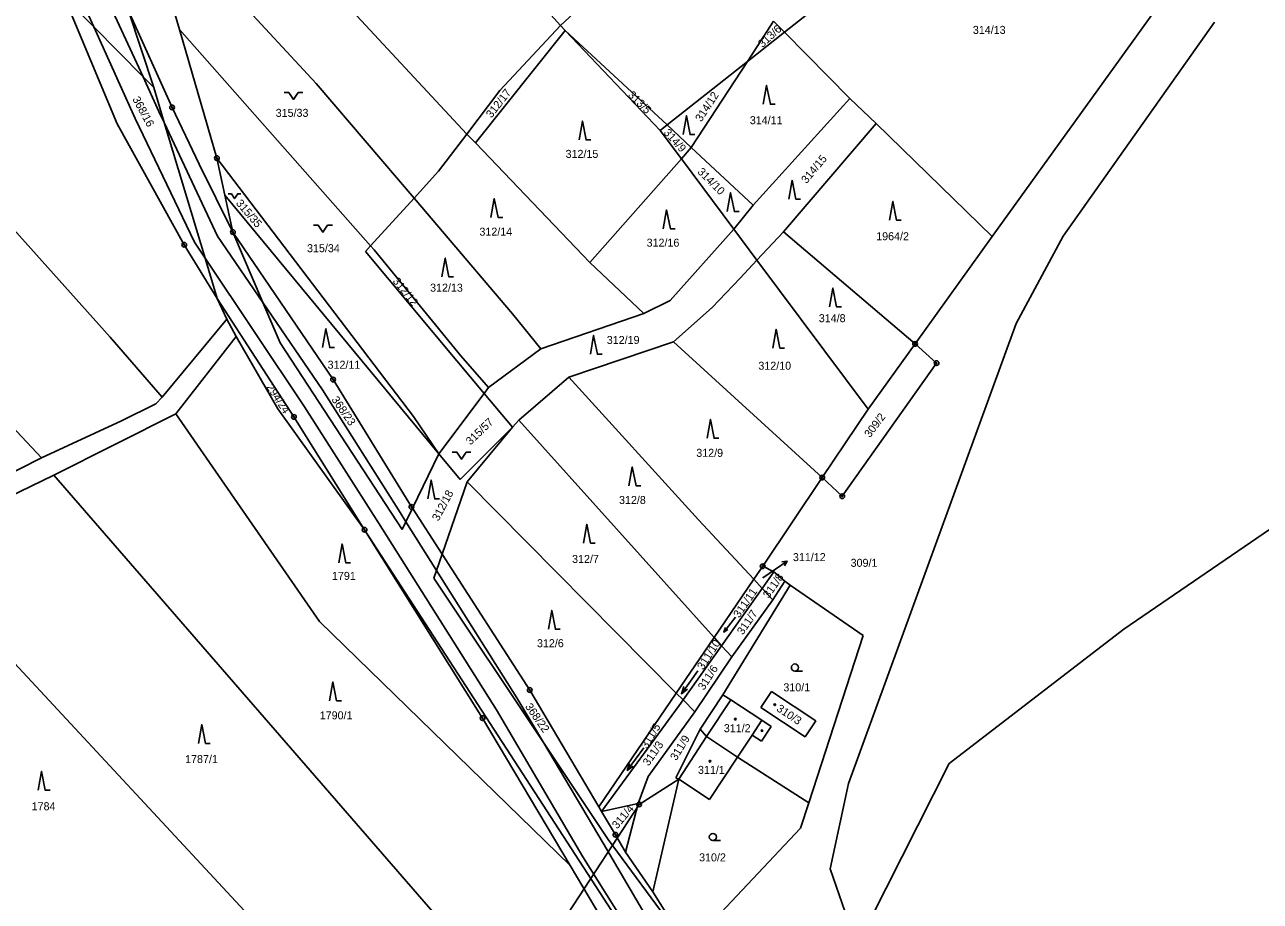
# Model space of a CAD drawing. Extents: x -762263 to -760336, y -1154405 to -1152076.
# Drawn here: x -761124.8 to -760862.4, y -1153687.5 to -1153501.2 of the extents above; entities that cross this region are included whole.
import ezdxf

# ---------------------------------------------------------------- set-up
doc = ezdxf.new("R2010")
doc.units = 0
for name, color, linetype in [('Vrstva 1', 7, 'Continuous'), ('Vrstva 12', 7, 'Continuous'), ('Vrstva 16', 7, 'Continuous'), ('Vrstva 18', 7, 'Continuous'), ('Vrstva 19', 7, 'Continuous'), ('Vrstva 24', 7, 'Continuous'), ('Vrstva 25', 7, 'Continuous'), ('Vrstva 26', 7, 'Continuous'), ('Vrstva 4', 7, 'Continuous'), ('Vrstva 6', 7, 'Continuous')]:
    doc.layers.add(name, color=color, linetype=linetype)

msp = doc.modelspace()

# ---------------------------------------------------------------- linework, layer by layer
at = {"layer": 'Vrstva 1'}
for p, q in [((-761091.93, -1153502.27), (-761100.45, -1153473.04)), ((-760987.13, -1153479.09), (-761010.99, -1153501.39)), ((-760963.41, -1153502.81), (-760952.38, -1153494.09)), ((-760882.41, -1153494.9), (-760919.31, -1153546.23)), ((-761105.15, -1153522.27), (-761116.32, -1153495.42)), ((-761116.32, -1153495.42), (-761110.14, -1153501.67)), ((-761102.76, -1153498.28), (-761097.38, -1153514.59)), ((-761102.76, -1153498.28), (-761093.48, -1153518.8)), ((-761110.14, -1153501.67), (-761099.65, -1153512.3)), ((-761083.97, -1153529.55), (-761091.93, -1153502.27)), ((-761023.87, -1153515.18), (-761010.99, -1153501.39)), ((-761010.99, -1153501.39), (-761009.97, -1153502.47)), ((-761009.97, -1153502.47), (-760989.84, -1153523.7)), ((-760971.3, -1153509.04), (-760963.41, -1153502.81)), ((-760904.22, -1153546.18), (-760872.1, -1153500.69)), ((-760988.36, -1153522.53), (-760971.3, -1153509.04)), ((-761099.65, -1153512.3), (-761097.38, -1153514.59)), ((-761097.38, -1153514.59), (-761095.14, -1153522.03)), ((-761030.9, -1153524.45), (-761023.87, -1153515.18)), ((-761093.48, -1153518.8), (-761087.72, -1153530.82)), ((-761090.9, -1153547.97), (-761105.15, -1153522.27)), ((-761095.14, -1153522.03), (-761086.48, -1153550.81)), ((-760989.84, -1153523.7), (-760988.36, -1153522.53)), ((-760989.84, -1153523.7), (-760985.32, -1153529.75)), ((-761036.88, -1153532.35), (-761030.9, -1153524.45)), ((-761080.57, -1153545.28), (-761087.72, -1153530.82)), ((-761082.27, -1153537.41), (-761083.97, -1153529.55)), ((-760985.32, -1153529.75), (-760974.21, -1153544.64)), ((-761036.88, -1153532.35), (-761042.1, -1153538.08)), ((-761080.57, -1153545.28), (-761082.27, -1153537.41)), ((-761036.81, -1153592.37), (-761082.27, -1153537.41)), ((-761042.1, -1153538.08), (-761051.32, -1153548.2)), ((-760974.21, -1153544.64), (-760969.27, -1153551.26)), ((-761059.28, -1153576.62), (-761080.57, -1153545.28)), ((-761074.19, -1153560.24), (-761080.57, -1153545.28)), ((-760919.31, -1153546.23), (-760935.7, -1153569.04)), ((-760914.21, -1153564.73), (-760904.22, -1153546.18)), ((-761083.9, -1153559.37), (-761090.9, -1153547.97)), ((-761051.32, -1153548.2), (-761052.43, -1153549.41)), ((-761052.43, -1153549.41), (-761032.98, -1153572.64)), ((-761086.48, -1153550.81), (-761083.9, -1153559.37)), ((-760969.27, -1153551.26), (-760945.65, -1153582.89)), ((-761083.9, -1153559.37), (-761067.6, -1153584.56)), ((-761070.53, -1153568.81), (-761074.19, -1153560.24)), ((-760949.86, -1153662.45), (-760914.21, -1153564.73)), ((-761070.53, -1153568.81), (-761044.6, -1153608.48)), ((-760935.7, -1153569.04), (-760945.65, -1153582.89)), ((-760931.12, -1153573.12), (-760935.7, -1153569.04)), ((-761032.98, -1153572.64), (-761027.19, -1153579.55)), ((-760951.17, -1153601.41), (-760931.12, -1153573.12)), ((-761042.66, -1153603.67), (-761059.28, -1153576.62)), ((-761027.19, -1153579.55), (-761021.16, -1153586.76)), ((-760945.65, -1153582.89), (-760955.42, -1153597.46)), ((-760824.24, -1153583.74), (-760891.34, -1153629.63)), ((-761052.6, -1153608.54), (-761067.6, -1153584.56)), ((-761032.28, -1153597.85), (-761021.16, -1153586.76)), ((-761032.28, -1153597.85), (-761036.81, -1153592.37)), ((-760955.42, -1153597.46), (-760968.06, -1153616.3)), ((-760955.42, -1153597.46), (-760951.17, -1153601.41)), ((-761042.46, -1153603.97), (-761043.82, -1153606.84)), ((-761042.46, -1153603.97), (-761042.66, -1153603.67)), ((-761036.15, -1153613.74), (-761042.46, -1153603.97)), ((-761043.82, -1153606.84), (-761044.6, -1153608.48)), ((-760991.27, -1153703.15), (-761052.6, -1153608.54)), ((-761027.56, -1153648.57), (-761052.6, -1153608.54)), ((-761036.15, -1153613.74), (-761037.31, -1153617.17)), ((-761017.51, -1153642.59), (-761036.15, -1153613.74)), ((-761037.31, -1153617.17), (-761037.88, -1153618.84)), ((-760969.94, -1153619.06), (-760968.06, -1153616.3)), ((-760968.14, -1153621), (-760965.66, -1153617.51)), ((-760965.66, -1153617.51), (-760968.06, -1153616.3)), ((-760965.66, -1153617.51), (-760963.32, -1153619.43)), ((-761037.88, -1153618.84), (-761014.63, -1153653.72)), ((-760978.35, -1153631.41), (-760969.94, -1153619.06)), ((-760976.78, -1153633.18), (-760968.14, -1153621)), ((-760962.22, -1153620.34), (-760976.49, -1153643.6)), ((-760963.32, -1153619.43), (-760962.22, -1153620.34)), ((-760962.22, -1153620.34), (-760946.74, -1153631.04)), ((-760978.35, -1153631.41), (-760986.41, -1153643.24)), ((-760958.24, -1153666.57), (-760946.74, -1153631.04)), ((-760891.34, -1153629.63), (-760928.42, -1153658.17)), ((-760976.78, -1153633.18), (-760984.96, -1153644.7)), ((-761002.85, -1153667.38), (-761017.51, -1153642.59)), ((-760986.41, -1153643.24), (-761002.85, -1153667.38)), ((-760976.49, -1153643.6), (-760981.33, -1153650.92)), ((-760976.49, -1153643.6), (-760974.81, -1153644.7)), ((-760968.44, -1153646.31), (-760966.21, -1153642.88)), ((-760966.21, -1153642.88), (-760956.77, -1153649.11)), ((-760985.78, -1153645.85), (-761002.26, -1153668.4)), ((-760984.96, -1153644.7), (-760985.78, -1153645.85)), ((-760968.24, -1153649.01), (-760974.81, -1153644.7)), ((-760959.01, -1153652.51), (-760968.44, -1153646.31)), ((-761027.56, -1153648.57), (-761008.97, -1153679.88)), ((-760966.25, -1153650.31), (-760968.24, -1153649.01)), ((-760956.77, -1153649.11), (-760959.01, -1153652.51)), ((-760981.33, -1153650.92), (-760986.48, -1153661.25)), ((-760981.33, -1153650.92), (-760979.98, -1153652.45)), ((-760979.98, -1153652.45), (-760973.42, -1153656.89)), ((-760973.42, -1153656.89), (-760970.32, -1153652.18)), ((-760970.32, -1153652.18), (-760968.33, -1153653.49)), ((-760968.33, -1153653.49), (-760966.25, -1153650.31)), ((-761014.63, -1153653.72), (-761000.86, -1153674.38)), ((-760973.42, -1153656.89), (-760979.33, -1153665.86)), ((-760958.24, -1153666.57), (-760973.42, -1153656.89)), ((-760928.42, -1153658.17), (-760945.15, -1153691.28)), ((-760985.85, -1153661.54), (-760991.4, -1153685.47)), ((-760986.48, -1153661.25), (-760985.85, -1153661.54)), ((-760979.33, -1153665.86), (-760985.85, -1153661.54)), ((-760953.71, -1153680.58), (-760949.86, -1153662.45)), ((-761002.26, -1153668.4), (-761002.85, -1153667.38)), ((-761002.26, -1153668.4), (-760994.47, -1153666.7)), ((-760997.21, -1153677.06), (-760994.47, -1153666.7)), ((-760959.99, -1153671.97), (-760958.24, -1153666.57)), ((-760999.33, -1153673.35), (-761002.26, -1153668.4)), ((-760999.33, -1153673.35), (-760997.21, -1153677.06)), ((-760983.9, -1153697.32), (-760959.99, -1153671.97)), ((-760983.9, -1153697.32), (-761000.86, -1153674.38)), ((-760997.21, -1153677.06), (-760991.4, -1153685.47)), ((-761008.97, -1153679.88), (-760995.71, -1153702.01)), ((-760945.38, -1153704.81), (-760953.71, -1153680.58)), ((-760991.4, -1153685.47), (-760983.9, -1153697.32))]:
    msp.add_line(p, q, dxfattribs=at)
at = {"layer": 'Vrstva 12'}
for p in [(-760985.85, -1153661.54), (-761009.38, -1153690)]:
    msp.add_line(p, (-760994.3, -1153666.9), dxfattribs=at)
at = {"layer": 'Vrstva 16'}
for p in [(-760962.875, -1153615.2), (-760968.02, -1153618.77)]:
    msp.add_line(p, (-760965.34, -1153616.91), dxfattribs=at)
msp.add_lwpolyline([(-760963.982, -1153615.359), (-760962.875, -1153615.2), (-760963.412, -1153616.181)], dxfattribs=at)
at = {"layer": 'Vrstva 24'}
for centre, radius in [((-761093.48, -1153518.8), 0.5), ((-761093.48, -1153518.8), 0.1), ((-761083.97, -1153529.55), 0.5), ((-761083.97, -1153529.55), 0.1), ((-761080.57, -1153545.28), 0.5), ((-761090.9, -1153547.97), 0.5), ((-761080.57, -1153545.28), 0.1), ((-761090.9, -1153547.97), 0.1), ((-760935.7, -1153569.04), 0.5), ((-760935.7, -1153569.04), 0.1), ((-760931.12, -1153573.12), 0.5), ((-760931.12, -1153573.12), 0.1), ((-761059.28, -1153576.62), 0.5), ((-761059.28, -1153576.62), 0.1), ((-761067.6, -1153584.56), 0.5), ((-761067.6, -1153584.56), 0.1), ((-760955.42, -1153597.46), 0.5), ((-760955.42, -1153597.46), 0.1), ((-760951.17, -1153601.41), 0.5), ((-760951.17, -1153601.41), 0.1), ((-761042.66, -1153603.67), 0.5), ((-761042.66, -1153603.67), 0.1), ((-761052.6, -1153608.54), 0.5), ((-761052.6, -1153608.54), 0.1), ((-760968.06, -1153616.3), 0.5), ((-760968.06, -1153616.3), 0.1), ((-761017.51, -1153642.59), 0.5), ((-761017.51, -1153642.59), 0.1), ((-761027.56, -1153648.57), 0.5), ((-761027.56, -1153648.57), 0.1), ((-760999.33, -1153673.35), 0.5), ((-760999.33, -1153673.35), 0.1)]:
    msp.add_circle(centre, radius, dxfattribs=at)
at = {"layer": 'Vrstva 25'}
for p, q in [((-760961.22, -1153638.56), (-760959.62, -1153638.56)), ((-760978.64, -1153674.57), (-760977.04, -1153674.57))]:
    msp.add_line(p, q, dxfattribs=at)
for points in [[(-761069.71, -1153515.6), (-761068.71, -1153515.6), (-761067.71, -1153517.1), (-761066.71, -1153515.6), (-761065.71, -1153515.6)], [(-760967.93, -1153518.11), (-760967.23, -1153514.11), (-760966.43, -1153518.11), (-760965.43, -1153518.11)], [(-760984.97, -1153524.56), (-760984.27, -1153520.56), (-760983.47, -1153524.56), (-760982.47, -1153524.56)], [(-761007.05, -1153525.7), (-761006.35, -1153521.7), (-761005.55, -1153525.7), (-761004.55, -1153525.7)], [(-760962.52, -1153538.28), (-760961.82, -1153534.28), (-760961.02, -1153538.28), (-760960.02, -1153538.28)], [(-760975.57, -1153540.93), (-760974.87, -1153536.93), (-760974.07, -1153540.93), (-760973.07, -1153540.93)], [(-761081.56, -1153537.145), (-761080.89, -1153537.145), (-761080.22, -1153538.15), (-761079.55, -1153537.145), (-761078.88, -1153537.145)], [(-761025.76, -1153542.18), (-761025.06, -1153538.18), (-761024.26, -1153542.18), (-761023.26, -1153542.18)], [(-760941.11, -1153542.77), (-760940.41, -1153538.77), (-760939.61, -1153542.77), (-760938.61, -1153542.77)], [(-760989.16, -1153544.57), (-760988.46, -1153540.57), (-760987.66, -1153544.57), (-760986.66, -1153544.57)], [(-761063.45, -1153543.83), (-761062.45, -1153543.83), (-761061.45, -1153545.33), (-761060.45, -1153543.83), (-761059.45, -1153543.83)], [(-761036.19, -1153554.8), (-761035.49, -1153550.8), (-761034.69, -1153554.8), (-761033.69, -1153554.8)], [(-760953.85, -1153561.17), (-760953.15, -1153557.17), (-760952.35, -1153561.17), (-760951.35, -1153561.17)], [(-761061.51, -1153569.83), (-761060.81, -1153565.83), (-761060.01, -1153569.83), (-761059.01, -1153569.83)], [(-760965.91, -1153569.92), (-760965.21, -1153565.92), (-760964.41, -1153569.92), (-760963.41, -1153569.92)], [(-761004.66, -1153571.24), (-761003.96, -1153567.24), (-761003.16, -1153571.24), (-761002.16, -1153571.24)], [(-760979.87, -1153589.1), (-760979.17, -1153585.1), (-760978.37, -1153589.1), (-760977.37, -1153589.1)], [(-761034.01, -1153592.06), (-761033.01, -1153592.06), (-761032.01, -1153593.56), (-761031.01, -1153592.06), (-761030.01, -1153592.06)], [(-760996.46, -1153599.18), (-760995.76, -1153595.18), (-760994.96, -1153599.18), (-760993.96, -1153599.18)], [(-761039.19, -1153601.97), (-761038.49, -1153597.97), (-761037.69, -1153601.97), (-761036.69, -1153601.97)], [(-761006.11, -1153611.38), (-761005.41, -1153607.38), (-761004.61, -1153611.38), (-761003.61, -1153611.38)], [(-761058.09, -1153615.54), (-761057.39, -1153611.54), (-761056.59, -1153615.54), (-761055.59, -1153615.54)], [(-761013.57, -1153629.67), (-761012.87, -1153625.67), (-761012.07, -1153629.67), (-761011.07, -1153629.67)], [(-760973.831, -1153627.125), (-760976.329, -1153630.275), (-760975.442, -1153629.696)], [(-760976.329, -1153630.275), (-760975.967, -1153629.279)], [(-760981.818, -1153638.487), (-760985.302, -1153643.373), (-760984.024, -1153642.442)], [(-761060.04, -1153644.88), (-761059.34, -1153640.88), (-761058.54, -1153644.88), (-761057.54, -1153644.88)], [(-760985.302, -1153643.373), (-760984.838, -1153641.861)], [(-761087.88, -1153653.92), (-761087.18, -1153649.92), (-761086.38, -1153653.92), (-761085.38, -1153653.92)], [(-760993.265, -1153654.859), (-760996.835, -1153659.681), (-760995.541, -1153658.773)], [(-761121.91, -1153663.89), (-761121.21, -1153659.89), (-761120.41, -1153663.89), (-761119.41, -1153663.89)], [(-760996.835, -1153659.681), (-760996.344, -1153658.178)]]:
    msp.add_lwpolyline(points, dxfattribs=at)
for centre, radius in [((-760961.22, -1153637.81), 0.75), ((-760965.49, -1153645.71), 0.175), ((-760973.88, -1153648.78), 0.175), ((-760968.19, -1153651.22), 0.175), ((-760979.24, -1153657.72), 0.175), ((-760978.64, -1153673.82), 0.75)]:
    msp.add_circle(centre, radius, dxfattribs=at)
at = {"layer": 'Vrstva 26'}
msp.add_circle((-760994.3, -1153666.9), 0.5, dxfattribs=at)
at = {"layer": 'Vrstva 4'}
for p, q in [((-761110.14, -1153501.67), (-761117.86, -1153484.57)), ((-761099.65, -1153512.3), (-761113.39, -1153482.44)), ((-761101.36, -1153521.14), (-761110.14, -1153501.67)), ((-761096.27, -1153519.63), (-761099.65, -1153512.3)), ((-761101.36, -1153521.14), (-761088.75, -1153547.41)), ((-761095.14, -1153522.03), (-761096.27, -1153519.63)), ((-761083.81, -1153546.12), (-761095.14, -1153522.03)), ((-761088.75, -1153547.41), (-761086.48, -1153550.81)), ((-761074.19, -1153560.24), (-761083.81, -1153546.12)), ((-761086.48, -1153550.81), (-761065.36, -1153582.42)), ((-761061.55, -1153578.78), (-761074.19, -1153560.24)), ((-761061.55, -1153578.78), (-761045.07, -1153604.85)), ((-761049.66, -1153607.1), (-761065.36, -1153582.42)), ((-761045.07, -1153604.85), (-761043.82, -1153606.84)), ((-761024.58, -1153646.8), (-761049.66, -1153607.1)), ((-761043.82, -1153606.84), (-761037.31, -1153617.17)), ((-761020.27, -1153644.23), (-761037.31, -1153617.17)), ((-761014.63, -1153653.72), (-761020.27, -1153644.23)), ((-761024.58, -1153646.8), (-761006.25, -1153678.03)), ((-760979.98, -1153652.45), (-760974.81, -1153644.7)), ((-760970.32, -1153652.18), (-760968.24, -1153649.01)), ((-760985.85, -1153661.54), (-760979.98, -1153652.45)), ((-761001.92, -1153675.11), (-761014.63, -1153653.72)), ((-760987.93, -1153698.92), (-761001.92, -1153675.11)), ((-761006.25, -1153678.03), (-760992.1, -1153700.58))]:
    msp.add_line(p, q, dxfattribs=at)
at = {"layer": 'Vrstva 6'}
for p, q in [((-761100.45, -1153473.04), (-761062.86, -1153513.72)), ((-761031.98, -1153477.92), (-761010.99, -1153501.39)), ((-761183.36, -1153481.98), (-761106.64, -1153567.61)), ((-761058.49, -1153494.72), (-761030.9, -1153524.45)), ((-761051.32, -1153548.2), (-761091.93, -1153502.27)), ((-761029.04, -1153526.34), (-761009.97, -1153502.47)), ((-760988.36, -1153522.53), (-761009.97, -1153502.47)), ((-760965.76, -1153500.49), (-760971.3, -1153509.04)), ((-760965.76, -1153500.49), (-760963.41, -1153502.81)), ((-760963.41, -1153502.81), (-760949.55, -1153516.89)), ((-760971.3, -1153509.04), (-760983.23, -1153527.3)), ((-761062.86, -1153513.72), (-761042.1, -1153538.08)), ((-760970.05, -1153539.54), (-760949.55, -1153516.89)), ((-760943.93, -1153522.21), (-760949.55, -1153516.89)), ((-760983.23, -1153527.3), (-760988.36, -1153522.53)), ((-760963.63, -1153545.2), (-760943.93, -1153522.21)), ((-760943.93, -1153522.21), (-760919.31, -1153546.23)), ((-761030.9, -1153524.45), (-761029.04, -1153526.34)), ((-761004.79, -1153551.76), (-761029.04, -1153526.34)), ((-760983.23, -1153527.3), (-760985.32, -1153529.75)), ((-760983.23, -1153527.3), (-760970.05, -1153539.54)), ((-761083.97, -1153529.55), (-761042.21, -1153584.5)), ((-760985.32, -1153529.75), (-761004.79, -1153551.76)), ((-761171.68, -1153539.67), (-761121.21, -1153593.28)), ((-761042.1, -1153538.08), (-761021.17, -1153562.63)), ((-760974.21, -1153544.64), (-760970.05, -1153539.54)), ((-760987.68, -1153559.81), (-760974.21, -1153544.64)), ((-760963.63, -1153545.2), (-760969.27, -1153551.26)), ((-760963.63, -1153545.2), (-760935.7, -1153569.04)), ((-761050.58, -1153549.04), (-761051.32, -1153548.2)), ((-761032.16, -1153571.59), (-761050.58, -1153549.04)), ((-760993.32, -1153562.55), (-761004.79, -1153551.76)), ((-760969.27, -1153551.26), (-760972.84, -1153555.1)), ((-760972.84, -1153555.1), (-760978.81, -1153561.3)), ((-761083.9, -1153559.37), (-761081.89, -1153563.82)), ((-760993.32, -1153562.55), (-760987.68, -1153559.81)), ((-761021.17, -1153562.63), (-761015.16, -1153570.12)), ((-761015.16, -1153570.12), (-760993.32, -1153562.55)), ((-760978.81, -1153561.3), (-760986.97, -1153568.59)), ((-761095.56, -1153580.38), (-761081.89, -1153563.82)), ((-761081.89, -1153563.82), (-761079.85, -1153567.48)), ((-761095.56, -1153580.38), (-761106.64, -1153567.61)), ((-761092.7, -1153583.88), (-761079.85, -1153567.48)), ((-761079.85, -1153567.48), (-761071.01, -1153582.83)), ((-761026.32, -1153578.32), (-761015.16, -1153570.12)), ((-761009.22, -1153576.14), (-760986.97, -1153568.59)), ((-760986.97, -1153568.59), (-760955.42, -1153597.46)), ((-761026.32, -1153578.32), (-761032.16, -1153571.59)), ((-761019.83, -1153585.25), (-761009.22, -1153576.14)), ((-761009.22, -1153576.14), (-760981.67, -1153606.44)), ((-761026.32, -1153578.32), (-761027.19, -1153579.55)), ((-761096.97, -1153581.79), (-761095.56, -1153580.38)), ((-761027.19, -1153579.55), (-761036.81, -1153592.37)), ((-761118.57, -1153596.92), (-761092.7, -1153583.88)), ((-761104.21, -1153585.38), (-761096.97, -1153581.79)), ((-761062.18, -1153628.04), (-761092.7, -1153583.88)), ((-761071.01, -1153582.83), (-761052.6, -1153608.54)), ((-761121.21, -1153593.28), (-761104.21, -1153585.38)), ((-761042.21, -1153584.5), (-761036.81, -1153592.37)), ((-761030.79, -1153598.33), (-761021.16, -1153586.76)), ((-761021.16, -1153586.76), (-761019.83, -1153585.25)), ((-761019.83, -1153585.25), (-760978.35, -1153631.41)), ((-761152.76, -1153609.11), (-761121.21, -1153593.28)), ((-761036.81, -1153592.37), (-761042.46, -1153603.97)), ((-761150.08, -1153612.09), (-761118.57, -1153596.92)), ((-761118.57, -1153596.92), (-761028.35, -1153700.96)), ((-761036.15, -1153613.74), (-761030.79, -1153598.33)), ((-760986.41, -1153643.24), (-761030.79, -1153598.33)), ((-760981.67, -1153606.44), (-760969.94, -1153619.06)), ((-761150.08, -1153612.09), (-761049.56, -1153720.16)), ((-760969.94, -1153619.06), (-760968.14, -1153621)), ((-760968.14, -1153621), (-760965.91, -1153623.4)), ((-760965.91, -1153623.4), (-760963.32, -1153619.43)), ((-760974.59, -1153635.53), (-760965.91, -1153623.4)), ((-761008.97, -1153679.88), (-761062.18, -1153628.04)), ((-760978.35, -1153631.41), (-760976.78, -1153633.18)), ((-760976.78, -1153633.18), (-760974.59, -1153635.53)), ((-760982.49, -1153647.2), (-760974.59, -1153635.53)), ((-760984.96, -1153644.7), (-760986.41, -1153643.24)), ((-760992.41, -1153660.98), (-760982.49, -1153647.2)), ((-760982.49, -1153647.2), (-760984.96, -1153644.7)), ((-760994.47, -1153666.7), (-760992.41, -1153660.98))]:
    msp.add_line(p, q, dxfattribs=at)

# ---------------------------------------------------------------- texts
at = {"layer": 'Vrstva 16'}
msp.add_text('311/12', height=1.7, dxfattribs=at).set_placement((-760961.633, -1153615.2))
at = {"layer": 'Vrstva 18'}
for s, rotation, p in [('313/6', 42.39888, (-760968.087, -1153506.198)), ('312/17', 51.90998, (-761025.658, -1153521.172)), ('313/5', 315.47056, (-760996.797, -1153516.322)), ('314/12', 56.72282, (-760981.108, -1153521.989)), ('368/16', 298.33913, (-761101.977, -1153517.009)), ('314/9', 311.97552, (-760989.212, -1153524.252)), ('314/15', 50.1911, (-760958.739, -1153535.095)), ('314/10', 315.01219, (-760982.024, -1153532.627)), ('315/35', 310.54313, (-761080.038, -1153539.228)), ('312/12', 308.65236, (-761046.746, -1153555.761)), ('294/24', 303.09467, (-761073.551, -1153578.223)), ('368/23', 304.69896, (-761059.715, -1153580.895)), ('309/2', 52.9413, (-760945.282, -1153589.109)), ('315/57', 43.71668, (-761030.12, -1153590.656)), ('312/18', 62.22322, (-761036.901, -1153606.822)), ('311/8', 54.88936, (-760966.766, -1153623.237)), ('311/11', 55.51961, (-760973.045, -1153627.402)), ('311/7', 55.51961, (-760972.266, -1153631.015)), ('311/10', 57.18119, (-760980.7, -1153638.443)), ('311/6', 57.18119, (-760980.531, -1153642.773)), ('368/22', 304.92814, (-761018.594, -1153646.115)), ('311/5', 58.3844, (-760992.635, -1153655.215)), ('311/9', 58.55629, (-760986.403, -1153657.719)), ('311/3', 55.23313, (-760992.28, -1153658.861)), ('311/4', 49.84733, (-760998.947, -1153672.219))]:
    msp.add_text(s, height=1.7, rotation=rotation, dxfattribs=at).set_placement(p)
for s, height, p in [('314/13', 1.7, (-760923.42, -1153503.17)), ('315/33', 1.7, (-761071.482, -1153520.8)), ('314/11', 1.7, (-760970.785, -1153522.36)), ('312/15', 1.7, (-761009.914, -1153529.52)), ('312/14', 1.7, (-761028.217, -1153546.05)), ('312/16', 1.7, (-760992.707, -1153548.39)), ('1964/2', 1.7, (-760943.948, -1153547.02)), ('315/34', 1.7, (-761064.825, -1153549.56)), ('312/13', 1.7, (-761038.694, -1153557.95)), ('314/8', 1.7, (-760956.142, -1153564.43)), ('312/19', 1.7, (-761001.167, -1153569.06)), ('312/11', 1.7, (-761060.459, -1153574.32)), ('312/10', 1.7, (-760968.974, -1153574.53)), ('312/9', 1.7, (-760982.156, -1153593.04)), ('312/8', 1.7, (-760998.566, -1153603.06)), ('312/7', 1.7, (-761008.536, -1153615.59)), ('309/1', 1.7, (-760949.379, -1153616.41)), ('1791', 1.7, (-761059.527, -1153619.18)), ('311/12', 0.1, (-760968.211, -1153618.77)), ('312/6', 1.7, (-761015.986, -1153633.49)), ('310/1', 1.7, (-760963.663, -1153642.87)), ('1790/1', 1.7, (-761062.123, -1153648.82)), ('1787/1', 1.7, (-761090.723, -1153658.11)), ('1784', 1.7, (-761123.312, -1153668.13)), ('310/2', 1.7, (-760981.563, -1153679))]:
    msp.add_text(s, height=height, dxfattribs=at).set_placement(p)
at = {"layer": 'Vrstva 19'}
msp.add_text('310/3', height=1.7, rotation=326.18487, dxfattribs=at).set_placement((-760965.26, -1153646.911))
for s, p in [('311/2', (-760976.313, -1153651.55)), ('311/1', (-760981.803, -1153660.41))]:
    msp.add_text(s, height=1.7, dxfattribs=at).set_placement(p)

doc.saveas('drawing.dxf')
